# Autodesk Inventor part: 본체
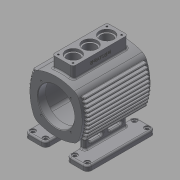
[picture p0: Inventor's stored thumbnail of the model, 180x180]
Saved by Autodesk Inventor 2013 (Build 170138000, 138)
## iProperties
Created: 2015-11
Part Number: 본체
Material: 알루미늄 6061
Document SubType Name: Modeling
Designer: mduedu
Density: 2.71 g/cm^3
Mass: 1542.18 g
Surface Area: 1694.56 cm^2
Volume: 569.07 cm^3
Author: mduedu
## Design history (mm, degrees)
sketch "스케치2"
  geometry: L1 (0, 250)-(0, -250); L2 (250, 0)-(-250, 0); L3 (-50, 50)-(50, 50); L4 (50, 50)-(50, -50); L5 (50, -50)-(-50, -50); L6 (-50, -50)-(-50, 50); A1 r 90 centre (-40, 0) between (40.415, -40.415) and (40.415, 40.415); A2 r 90 centre (40, 0) between (-40.415, 40.415) and (-40.415, -40.415); A3 r 90 centre (0, -40) between (40.415, 40.415) and (-40.415, 40.415); A4 r 90 centre (0, 40) between (-40.415, -40.415) and (40.415, -40.415); 2 further points
  constraints: 12 end point, 8 point on circle, 4 centre point, 4 tangent, 3 perpendicular, 2 horizontal alignment, 2 midpoint, 2 parallel, 2 symmetric about line, 1 coincident, 1 equal radius, 1 horizontal, 1 vertical, 1 vertical alignment, 2 other
  dimensions: "d6" = 500 distance of L1.start L1.end; "d8" = 500 distance of L2.start L2.end; "d9" = 100 distance of L3.end L4.end; "d11" = 90 radius of A3
extrude "돌출1" new body sketch "스케치2" stored distance "d12" = 130; taper "d13" = 0 deg
sketch "스케치3"
  geometry: A1 r 90 centre (40, 0) between (-40.415, 40.415) and (-40.415, -40.415) reference; 2 further points
  constraints: 1 point on circle
fillet "모깎기6" dims "d30" = 15
feature "쉘1" dims "d31" = 15, "d32" = 6, "d33" = 15
sketch "스케치4"
  geometry: L1 (60, -57)-(-60, -57); L2 (-65, 40.415)-(-65, -40.415) reference; L3 (65, -40.415)-(65, 40.415) reference; L4 (-60, -57)-(-60, -45); L5 (60, -57)-(60, -45); L6 (-65, -50)-(65, -50) reference; L7 (-60, -45)-(60, -45); 2 further points
  constraints: 8 end point, 2 parallel, 1 horizontal
  dimensions: "d16" = 5 distance between parallel lines of L7 L6; "d17" = 12 distance of L1.start L5.end; "d23" = 5 distance between parallel lines of L4 L2; "d24" = 5 distance between parallel lines of L5 L3
extrude "돌출2" new body sketch "스케치4" stored distance "d18" = 3; taper "d19" = 0 deg
fillet "모깎기1" dims "d20" = 3
fillet "모깎기4" dims "d25" = 1
sketch "스케치5"
  geometry: C1 r 35 at (0, 0); 1 further point
  constraints: 1 centre point, 1 coincident
  dimensions: "d34" = 70 diameter of C1
extrude "돌출3" cut sketch "스케치5" stored distance "d36" = 3; taper "d37" = 0 deg
feature "결합1"
  node "솔리드2"
fillet "모깎기7" dims "d38" = 1
fillet "모깎기8" dims "d39" = 1
node "작업 평면1"
sketch "스케치6"
  geometry: L1 (-65, -60)-(65, -60); L2 (65, -60)-(65, 60); L3 (65, 60)-(-65, 60); L4 (-65, 60)-(-65, -60); L5 (-65, -60)-(65, 60); L6 (65, -60)-(-65, 60); 1 further point
  constraints: 12 end point, 2 midpoint, 2 parallel, 1 horizontal, 1 perpendicular
  dimensions: "d41" = 120 distance of L3.end L1.start; "d43" = 130 distance of L2.end L3.end
extrude "돌출4" join sketch "스케치6" distance "d44" = 10; taper "d45" = 0 deg
sketch "스케치8"
  geometry: L1 (-60, -70)-(60, -70) reference; L2 (0, -50)-(0, -70); L3 (-30, -44.853)-(-30, -70); L4 (30, -44.853)-(30, -70); L5 (-30, -70)-(30, -70); A1 r 90 centre (0, 40) between (-34.941, -42.941) and (34.941, -42.941) reference; A2 r 90 centre (0, 40) between (-30, -44.853) and (30, -44.853); 1 further point
  constraints: 8 end point, 5 point on circle, 2 perpendicular, 2 symmetric about line, 1 centre point, 1 midpoint, 1 point on line
  dimensions: "d48" = 60 distance between parallel lines of L4 L3
extrude "돌출5" join sketch "스케치8" stored distance "d50" = 80; taper "d51" = 0 deg
sketch "스케치9"
  geometry: L1 (-30, -44.853)-(-30, -70) reference; L2 (30, -70)-(30, -44.853) reference; L3 (-20, -47.75)-(-20, -80); L4 (20, -80)-(20, -47.75); L5 (-48.917, -80)-(48.917, -80) reference; A1 r 90 centre (0, 40) between (-34.941, -42.941) and (34.941, -42.941) reference; 1 further point
  constraints: 4 end point, 2 parallel, 2 point on circle, 2 point on line
  dimensions: "d52" = 10 distance between parallel lines of L2 L4; "d54" = 10 distance between parallel lines of L1 L3 (derived)
extrude "돌출6" cut sketch "스케치9" stored distance "d55" = 80; taper "d56" = 0 deg
fillet "모깎기9" dims "d57" = 8
sketch "스케치10"
  geometry: A1 r 8 centre (-57, 52) between (-57, 60) and (-65, 52) reference; A2 r 8 centre (57, 52) between (65, 52) and (57, 60) reference; A3 r 8 centre (57, 28) between (57, 20) and (65, 28) reference; A4 r 8 centre (-57, 28) between (-65, 28) and (-57, 20) reference; A5 r 8 centre (-57, -28) between (-57, -20) and (-65, -28) reference; A6 r 8 centre (-57, -52) between (-65, -52) and (-57, -60) reference; A7 r 8 centre (57, -52) between (57, -60) and (65, -52) reference; A8 r 8 centre (57, -28) between (65, -28) and (57, -20) reference; 1 further point
hole "구멍1" sketch "스케치10" at (-57, 52), (57, 52), (57, 28), (-57, 28), (-57, -28), (-57, -52), (57, -52), (57, -28) diameter "d58" = 6; stored, may be unused: countersink angle "d62" = 90 deg, drill point angle "d64" = 118 deg; dims "d59" = 6, "d60" = 10, "d61" = 2, "d63" = 8
fillet "모깎기10" dims "d65" = 3
fillet "모깎기11" dims "d66" = 3
fillet "모깎기12" dims "d67" = 3
sketch "스케치11" dims "d72" = 25
  geometry: L1 (65, -50)-(-65, -50) reference; L2 (-80.5, -80)-(80.5, -80) reference; L3 (0, -50)-(0, -80); L4 (-27, -54)-(-10, -54); L5 (-10, -54)-(-10, -62); L6 (-10, -62)-(-27, -62); L7 (-27, -62)-(-27, -54); 3 further points
  constraints: 10 end point, 4 midpoint, 2 parallel, 2 perpendicular, 2 vertical alignment, 1 horizontal, 4 other
  dimensions: "d68" = 8 distance between parallel lines of L6 L4; "d71" = 8 distance from line of point (-27, -58) L1; "d73" = 6 dimension on L3
extrude "돌출7" cut sketch "스케치11" stored distance "d74" = 80; taper "d75" = 0 deg
fillet "모깎기13" dims "d76" = 3
fillet "모깎기14" dims "d78" = 3
sketch "스케치12"
  geometry: L1 (0, 0)-(28.284, 28.284); L2 (0, 0)-(40, 0); A1 r 40 centre (0, 0) between (28.284, 28.284) and (40, 0); 2 further points
  constraints: 4 end point, 2 coincident, 2 point on circle, 1 centre point, 1 horizontal
  dimensions: "d79" = 80 diameter of A1; "d80" = 45 deg angle of L2 L1
hole "구멍2" sketch "스케치12" at (28.284, 28.284) diameter "d82" = 3.242; stored, may be unused: countersink angle "d86" = 90 deg, drill point angle "d88" = 118 deg; dims "d83" = 9, "d84" = 10, "d85" = 2, "d87" = 11
node "작업 평면2"
sketch "스케치13"
  geometry: L1 (-52.5, -20)-(52.5, -20); L2 (52.5, -20)-(52.5, 20); L3 (52.5, 20)-(-52.5, 20); L4 (-52.5, 20)-(-52.5, -20); L5 (-52.5, -20)-(52.5, 20); L6 (52.5, -20)-(-52.5, 20); 1 further point
  constraints: 12 end point, 2 midpoint, 2 parallel, 1 horizontal, 1 perpendicular
  dimensions: "d93" = 105 distance of L2.end L3.end; "d95" = 40 distance of L1.end L2.end
extrude "돌출8" join sketch "스케치13" stored distance "d96" = 80; taper "d97" = 0 deg
fillet "모깎기15" dims "d98" = 5
fillet "모깎기16" dims "d99" = 3
sketch "스케치14"
  geometry: L1 (-52.5, 15)-(-52.5, -15) reference; L2 (52.5, -15)-(52.5, 15) reference; L3 (-52.5, 0)-(52.5, 0); 4 further points
  constraints: 2 end point, 2 midpoint, 2 point on line, 1 coincident
  dimensions: "d100" = 32 distance of point (-32, 0) point (0, 0); "d102" = 32 distance of point (32, 0) point (0, 0) (derived)
hole "구멍3" sketch "스케치14" at (-32, 0), (0, 0), (32, 0) diameter "d103" = 22; stored, may be unused: countersink angle "d107" = 90 deg, drill point angle "d109" = 118 deg; dims "d104" = 8, "d105" = 28, "d106" = 5, "d108" = 10
sketch "스케치15"
  geometry: L1 (46.5, -14)-(-46.5, -14); L2 (-46.5, -14)-(-46.5, 14); L3 (-46.5, 14)-(46.5, 14); L4 (46.5, 14)-(46.5, -14); L5 (46.5, -14)-(-46.5, 14); L6 (-46.5, -14)-(46.5, 14); L7 (47.5, 20)-(-47.5, 20) reference; L8 (-52.5, 15)-(-52.5, -15) reference; 5 further points
  constraints: 12 end point, 4 coincident, 2 midpoint, 2 parallel, 1 horizontal, 1 perpendicular
  dimensions: "d110" = 6 distance between parallel lines of L3 L7; "d111" = 6 distance between parallel lines of L2 L8
hole "구멍4" sketch "스케치15" at (-46.5, 14), (46.5, 14), (46.5, -14), (-46.5, -14) diameter "d112" = 3.242; stored, may be unused: countersink angle "d116" = 90 deg, drill point angle "d118" = 118 deg; dims "d113" = 10, "d114" = 28, "d115" = 5, "d117" = 13
sketch "스케치16"
  geometry: L1 (33.5, 0)-(61.5, 0) reference; L2 (104.5, -150)-(-9.5, -150) reference; L3 (47.5, 0)-(47.5, -150); 2 further points
  constraints: 2 end point, 2 midpoint, 1 point on line, 1 other
  dimensions: "d122" = 11 distance from line of point (47.5, -11) L1
feature "엠보싱2" sketch "스케치16" dims "d16" = 5, "d17" = 12, "d23" = 5, "d24" = 5, "d123" = 0.5, "d124" = 0
chamfer "모따기1" distance "d125" = 1; stored, may be unused: second distance "d126" = 2, angle "d127" = 45 deg
node "솔리드1"
pattern_linear "직사각형 패턴1" dims "d29" = 7
mirror "대칭1"
mirror "대칭2"
pattern_circular "원형 패턴1" dims angle "d90" = 360 deg
mirror "대칭3"
